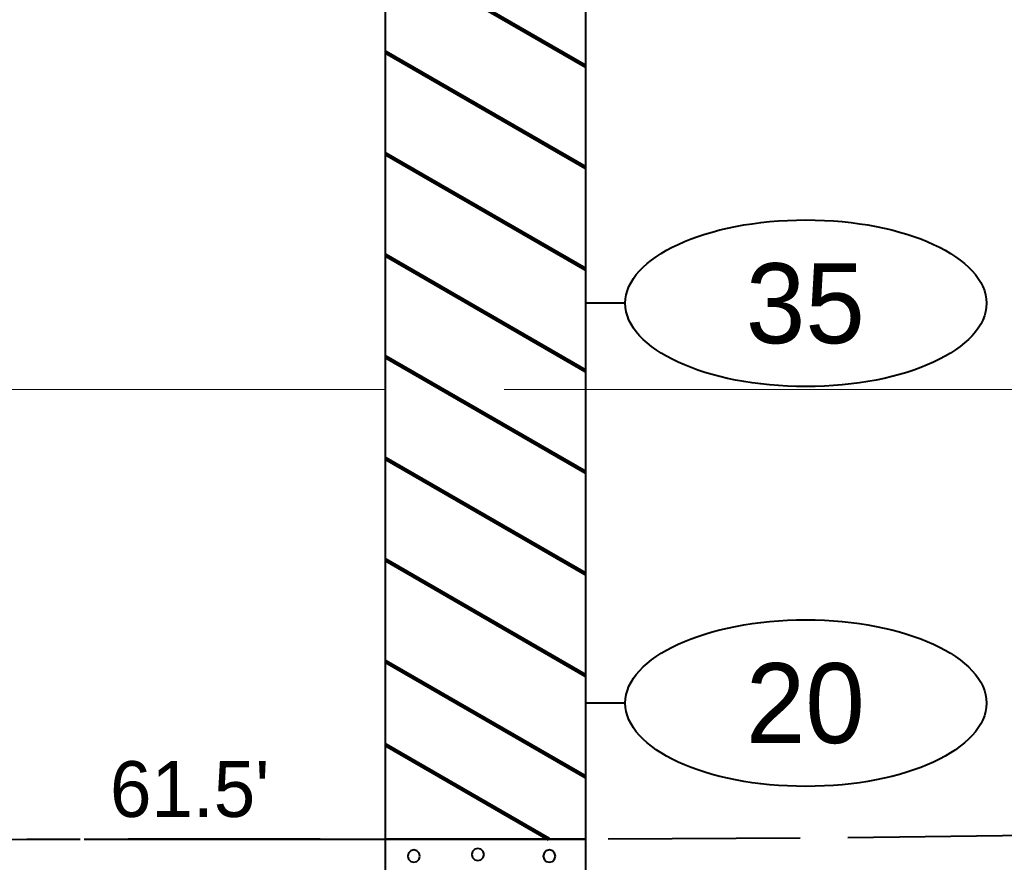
# Model space of a CAD drawing. Extents: x -582 to 653, y -817 to -3.
# Drawn here: x -30.04 to -17.73, y -550.04 to -539.51 of the extents above; entities that cross this region are included whole.
import ezdxf
from ezdxf.enums import TextEntityAlignment as Align

# ---------------------------------------------------------------- set-up
doc = ezdxf.new("R2010")
doc.units = 0
doc.header["$LTSCALE"] = 0.4
doc.linetypes.add('LONG_DASHED', pattern=[7.5, 6, -1.5])
for name, color, linetype, lineweight in [('26', 7, 'LONG_DASHED', 40), ('27', 7, 'Continuous', 40), ('7', 7, 'Continuous', 13)]:
    doc.layers.add(name, color=color, linetype=linetype, lineweight=lineweight)

msp = doc.modelspace()

# ---------------------------------------------------------------- linework, layer by layer
at = {"layer": '26'}
msp.add_spline([(-40.6865, -549.8893), (-29.2387, -549.7528), (-25.4713, -549.7528), (-22.9713, -549.7528), (23.7613, -548.7128), (27.5287, -548.7128), (30.0287, -548.7128), (46.0791, -548.7128)], degree=3, dxfattribs=at)
at = {"layer": '27', "lineweight": 158}
for p, q in [((-25.4713, -538.6428), (-22.9713, -540.0862)), ((-25.4713, -539.9128), (-22.9713, -541.3562)), ((-25.4713, -541.1828), (-22.9713, -542.6262)), ((-25.4713, -542.4528), (-22.9713, -543.8962)), ((-25.4713, -543.7228), (-22.9713, -545.1662)), ((-25.4713, -544.9928), (-22.9713, -546.4362)), ((-25.4713, -546.2628), (-22.9713, -547.7062)), ((-25.4713, -547.5328), (-22.9713, -548.9762)), ((-25.4713, -548.5726), (-23.4271, -549.7528))]:
    msp.add_line(p, q, dxfattribs=at)
at = {"layer": '27'}
for p, q in [((-22.4714, -543.0528), (-22.9714, -543.0528)), ((-22.4714, -548.0528), (-22.9714, -548.0528)), ((-29.2387, -549.7528), (-25.4713, -549.7528))]:
    msp.add_line(p, q, dxfattribs=at)
for points in [[(-25.4713, -529.7528), (-22.9713, -529.7528), (-22.9713, -549.7528), (-25.4713, -549.7528)], [(-25.4713, -549.7528), (-22.9713, -549.7528), (-22.9713, -558.0528), (-25.4713, -558.0528)], [(-25.0394, -549.9655), (-25.0496, -549.9274), (-25.0775, -549.8995), (-25.1156, -549.8893), (-25.1537, -549.8995), (-25.1816, -549.9274), (-25.1918, -549.9655), (-25.1816, -550.0036), (-25.1537, -550.0314), (-25.1156, -550.0417), (-25.0775, -550.0314), (-25.0496, -550.0036)], [(-24.2384, -549.9459), (-24.2487, -549.9078), (-24.2765, -549.8799), (-24.3146, -549.8697), (-24.3527, -549.8799), (-24.3806, -549.9078), (-24.3908, -549.9459), (-24.3806, -549.984), (-24.3527, -550.0119), (-24.3146, -550.0221), (-24.2765, -550.0119), (-24.2487, -549.984)], [(-23.3448, -549.9655), (-23.355, -549.9274), (-23.3829, -549.8995), (-23.421, -549.8893), (-23.4591, -549.8995), (-23.487, -549.9274), (-23.4972, -549.9655), (-23.487, -550.0036), (-23.4591, -550.0315), (-23.421, -550.0417), (-23.3829, -550.0315), (-23.355, -550.0036)]]:
    msp.add_lwpolyline(points, close=True, dxfattribs=at)
for centre in [(-20.214, -543.0528), (-20.214, -548.0528)]:
    msp.add_ellipse(centre, major_axis=(2.2574, 0), ratio=0.461538, dxfattribs=at)
at = {"layer": '7'}
for p, q in [((-62.9147, -544.1328), (-25.4713, -544.1328)), ((-23.9857, -544.1328), (27.5287, -544.1328)), ((-22.9713, -544.1328), (28.379, -544.1328))]:
    msp.add_line(p, q, dxfattribs=at)

# ---------------------------------------------------------------- texts
at = {"layer": '27'}
for s, p in [('35', (-20.2214, -543.5528)), ('20', (-20.2213, -548.5528))]:
    msp.add_text(s, height=1, dxfattribs=at).set_placement(p, align=Align.CENTER)
msp.add_text("61.5'", height=0.6976, dxfattribs=at).set_placement((-28.9146, -549.4764))

doc.saveas('drawing.dxf')
